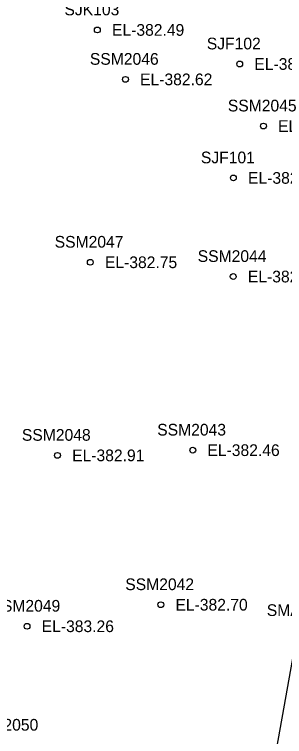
# Model space of a CAD drawing. Extents: x 1189978 to 1314812, y 571533 to 629339.
# Drawn here: x 1217264.2 to 1217356.4, y 620723.5 to 620970.5 of the extents above; entities that cross this region are included whole.
import ezdxf

# ---------------------------------------------------------------- set-up
doc = ezdxf.new("R2010")
doc.units = 0
for name, color, linetype in [('SURVEY - DTM - Breaklines', 7, 'Continuous'), ('SURVEY - DTM - Breaklines - Points - Numbers', 7, 'Continuous'), ('SURVEY - DTM - Spot Points - Elevations', 7, 'Continuous'), ('SURVEY - DTM - Spot Points - Locators', 7, 'Continuous'), ('SURVEY - DTM - Spot Points - Point Numbers', 7, 'Continuous')]:
    doc.layers.add(name, color=color, linetype=linetype)

msp = doc.modelspace()

# ---------------------------------------------------------------- linework, layer by layer
at = {"layer": 'SURVEY - DTM - Breaklines'}
msp.add_lwpolyline([(1217350.33, 620699.75), (1217360.97, 620759.72), (1217369.44, 620811.8), (1217380.12, 620871.2), (1217384.41, 620924.16), (1217387.31, 620948.08)], dxfattribs=at)
at = {"layer": 'SURVEY - DTM - Spot Points - Locators'}
for centre in [(1217292.52, 620965.18), (1217341.13, 620953.53), (1217302.11, 620948.27), (1217349.23, 620932.31), (1217338.97, 620914.56), (1217290.1, 620885.71), (1217338.92, 620880.82), (1217325.1, 620821.44), (1217278.9, 620819.66), (1217314.18, 620768.57), (1217268.51, 620761.2)]:
    msp.add_circle(centre, 1, dxfattribs=at)

# ---------------------------------------------------------------- texts
at = {"layer": 'SURVEY - DTM - Breaklines - Points - Numbers'}
msp.add_text('SMA249', height=4, dxfattribs=at).set_placement((1217350.38, 620764.72))
at = {"layer": 'SURVEY - DTM - Spot Points - Elevations'}
for s, p in [('EL-382.49', (1217297.52, 620963.18)), ('EL-382.07', (1217346.13, 620951.53)), ('EL-382.62', (1217307.11, 620946.27)), ('EL-382.16', (1217354.23, 620930.31)), ('EL-382.14', (1217343.97, 620912.56)), ('EL-382.75', (1217295.1, 620883.71)), ('EL-382.24', (1217343.92, 620878.82)), ('EL-382.46', (1217330.1, 620819.44)), ('EL-382.91', (1217283.9, 620817.66)), ('EL-382.70', (1217319.18, 620766.57)), ('EL-383.26', (1217273.51, 620759.2))]:
    msp.add_text(s, height=4, dxfattribs=at).set_placement(p)
at = {"layer": 'SURVEY - DTM - Spot Points - Point Numbers'}
for s, p in [('SJK103', (1217281.28, 620970.18)), ('SJF102', (1217329.89, 620958.53)), ('SSM2046', (1217289.97, 620953.27)), ('SSM2045', (1217337.07, 620937.31)), ('SJF101', (1217327.88, 620919.56)), ('SSM2047', (1217277.95, 620890.71)), ('SSM2044', (1217326.79, 620885.82)), ('SSM2043', (1217312.96, 620826.44)), ('SSM2048', (1217266.75, 620824.66)), ('SSM2042', (1217302.05, 620773.57)), ('SSM2049', (1217256.36, 620766.2)), ('SSM2050', (1217248.86, 620725.5))]:
    msp.add_text(s, height=4, dxfattribs=at).set_placement(p)

doc.saveas('drawing.dxf')
